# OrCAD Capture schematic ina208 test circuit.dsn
size A
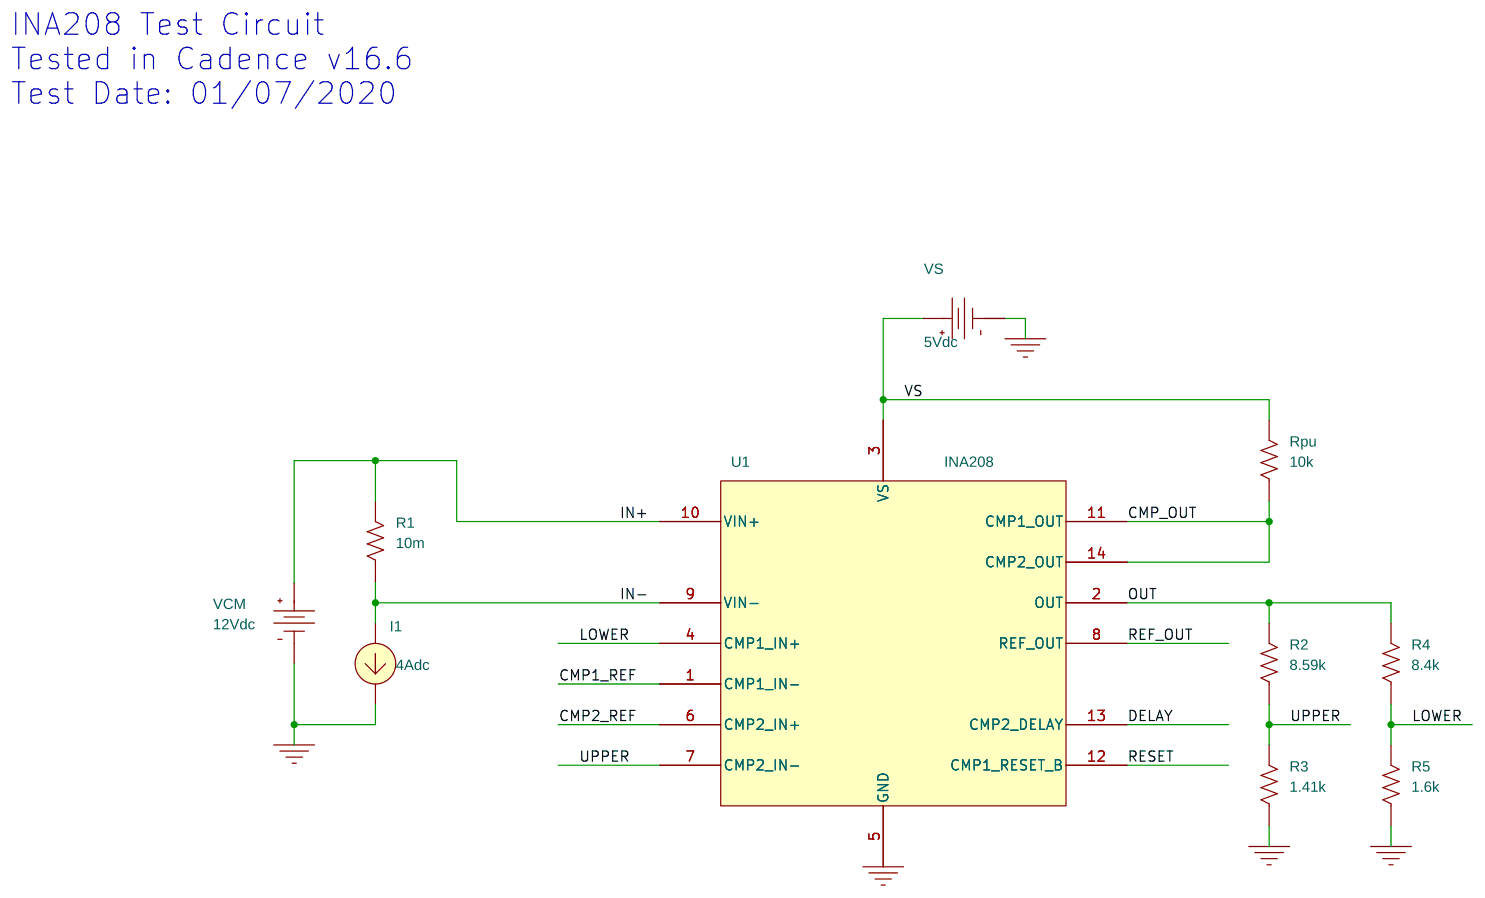
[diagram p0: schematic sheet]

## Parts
I1  IDC
R1  10m  [AX/RC05]
R2  8.59k  [AX/RC05]
R3  1.41k  [AX/RC05]
R4  8.4k  [AX/RC05]
R5  1.6k  [AX/RC05]
Rpu  10k  [AX/RC05]
U1  INA208
VCM  VDC
VS  VDC

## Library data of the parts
I1 = IDC: DC: 4Adc
R1-R5 Rpu = R
U1 = INA208
VCM = VDC: DC: 12Vdc
VS = VDC: DC: 5Vdc

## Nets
0: I1.2(-) R3.1 R5.1 U1.5(GND) VCM.1(-) VS.1(-)
CMP1_REF: U1.1(CMP1_IN-)
CMP2_REF: U1.6(CMP2_IN+)
CMP_OUT: Rpu.1 U1.11(CMP1_OUT) U1.14(CMP2_OUT)
DELAY: U1.13(CMP2_DELAY)
IN+: R1.2 U1.10(VIN+) VCM.0(+)
IN-: I1.1(+) R1.1 U1.9(VIN-)
LOWER: R4.1 R5.2 U1.4(CMP1_IN+)
OUT: R2.2 R4.2 U1.2(OUT)
REF_OUT: U1.8(REF_OUT)
RESET: U1.12(CMP1_RESET_B)
UPPER: R2.1 R3.2 U1.7(CMP2_IN-)
VS: Rpu.2 U1.3(VS) VS.0(+)

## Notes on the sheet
- INA208 Test Circuit
  Tested in Cadence v16.6
  Test Date: 01/07/2020
